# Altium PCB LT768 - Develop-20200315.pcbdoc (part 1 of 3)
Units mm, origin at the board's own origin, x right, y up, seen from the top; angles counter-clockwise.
Board outline 114.72 x 114.74 mm, 2 copper layers (Top Layer, Bottom Layer); 164 components, 138 nets, 704 pads, 858 vias.
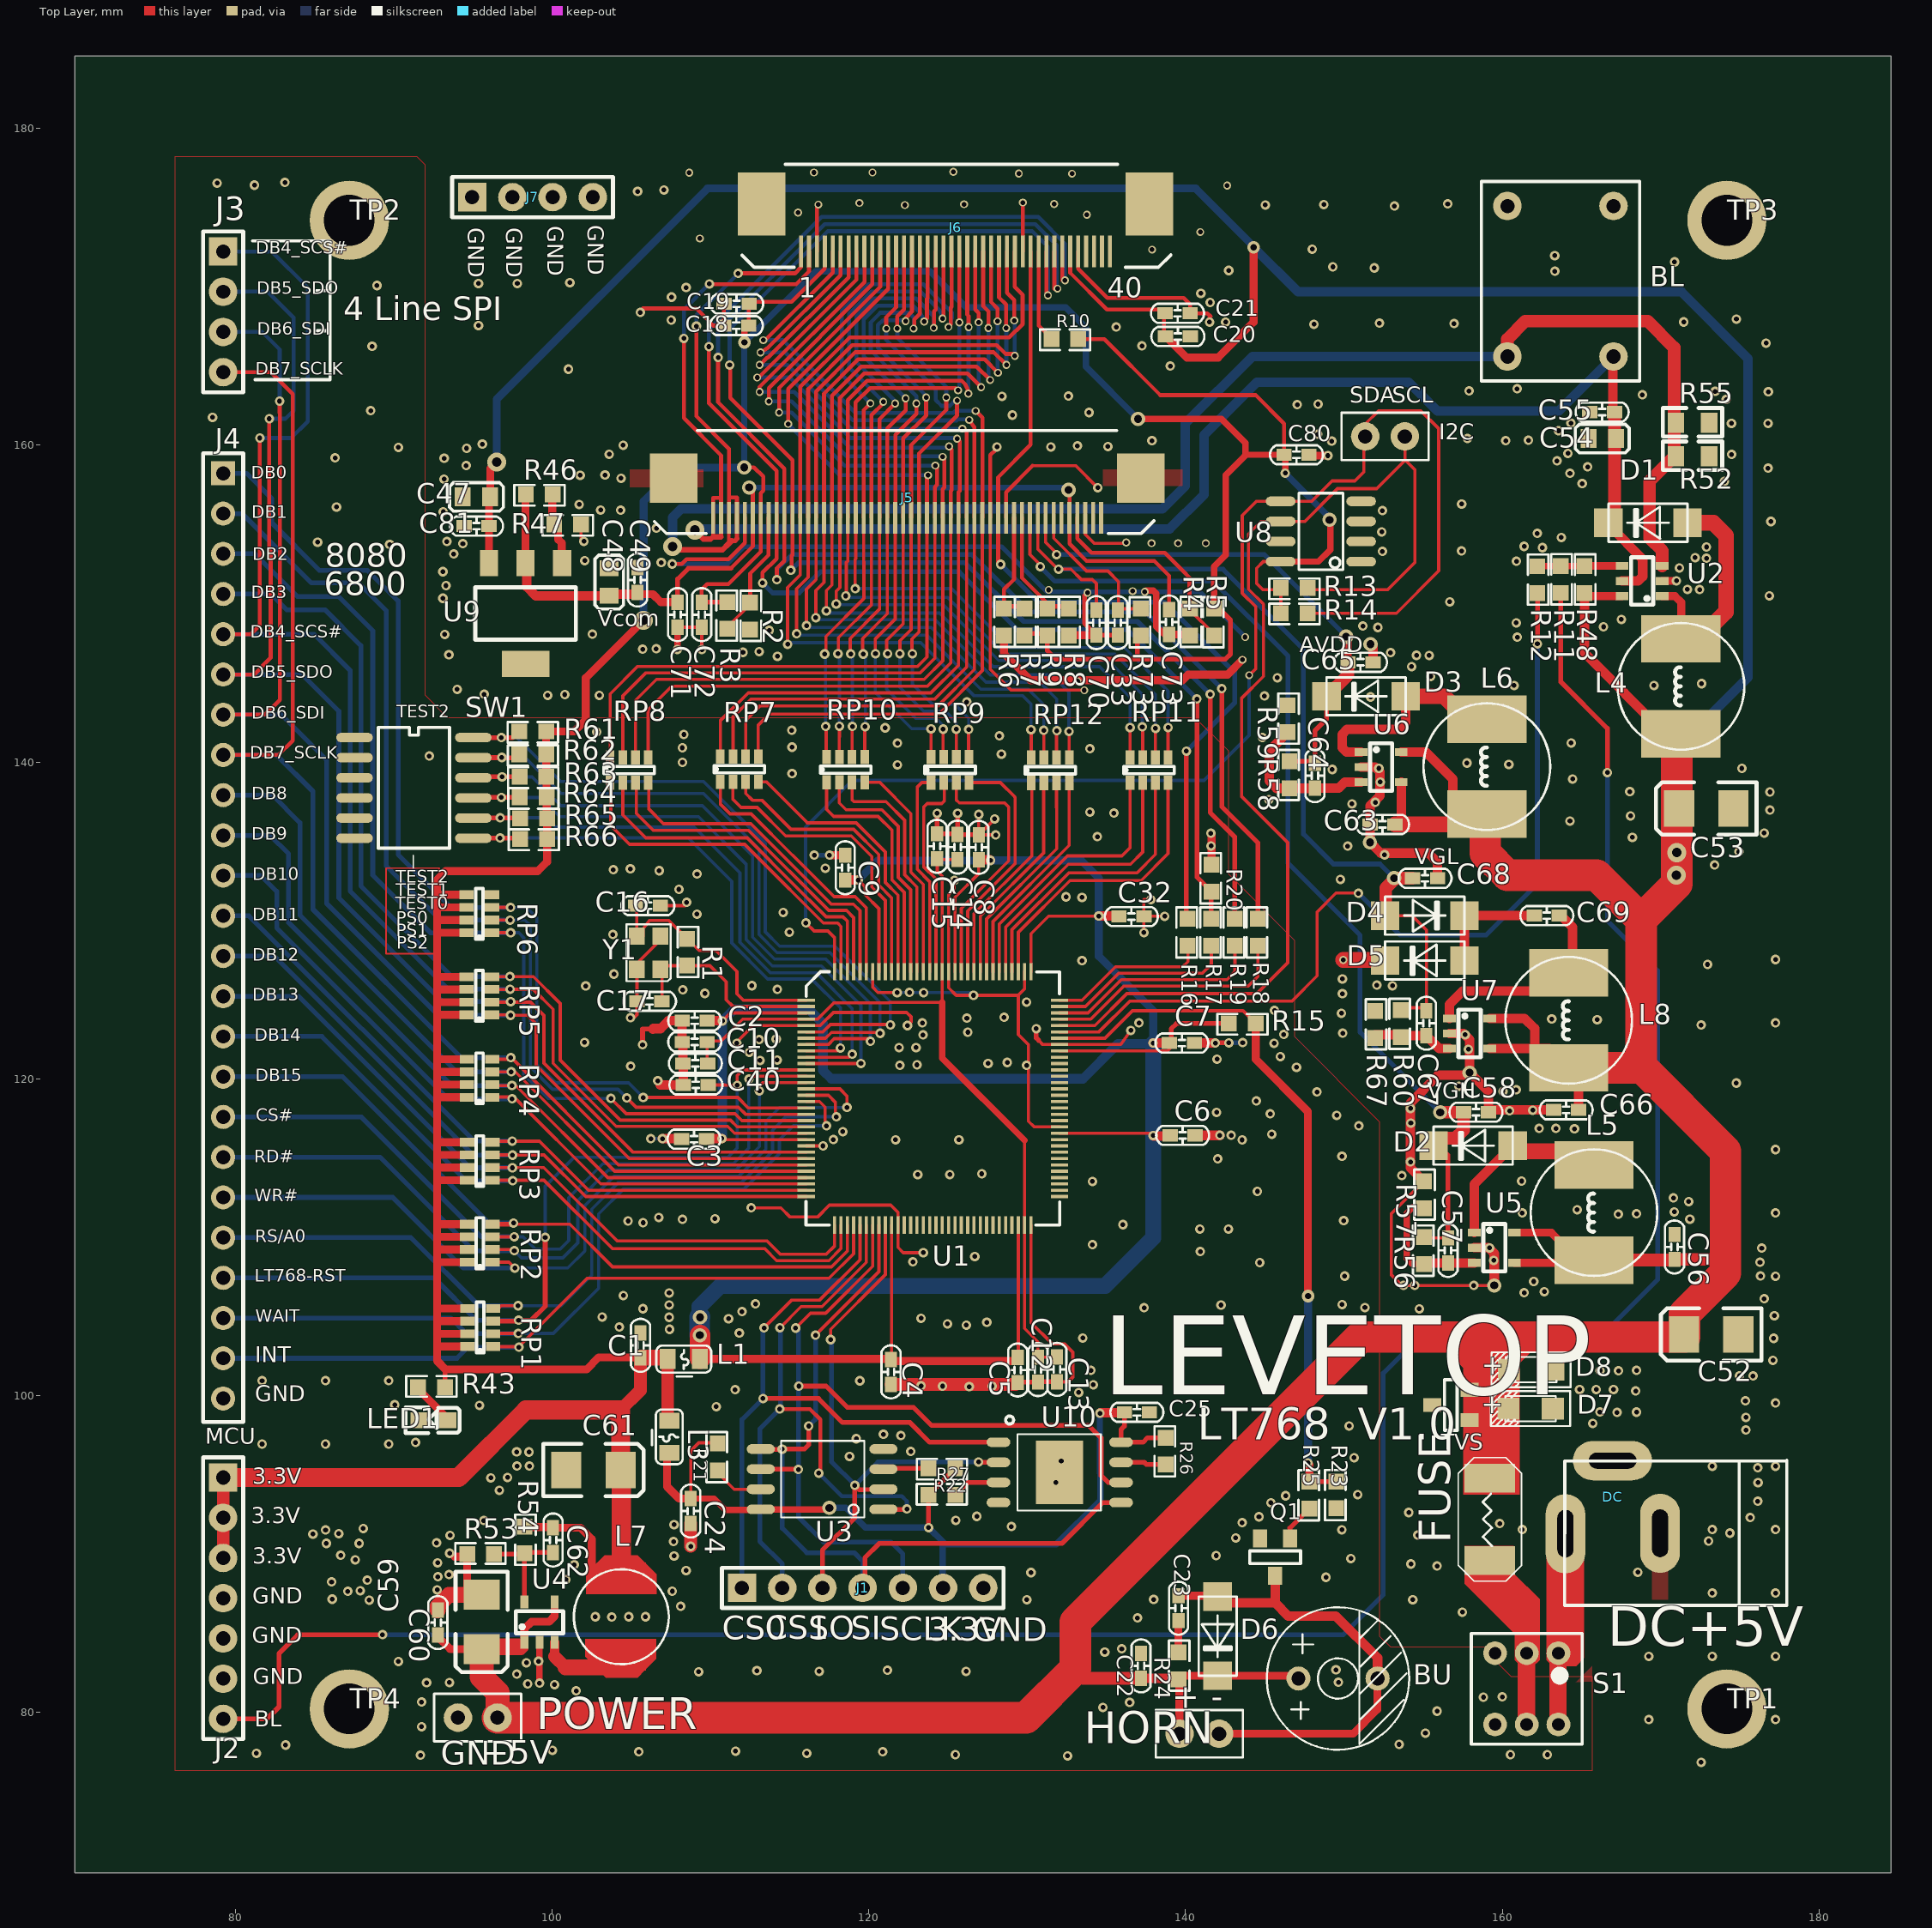
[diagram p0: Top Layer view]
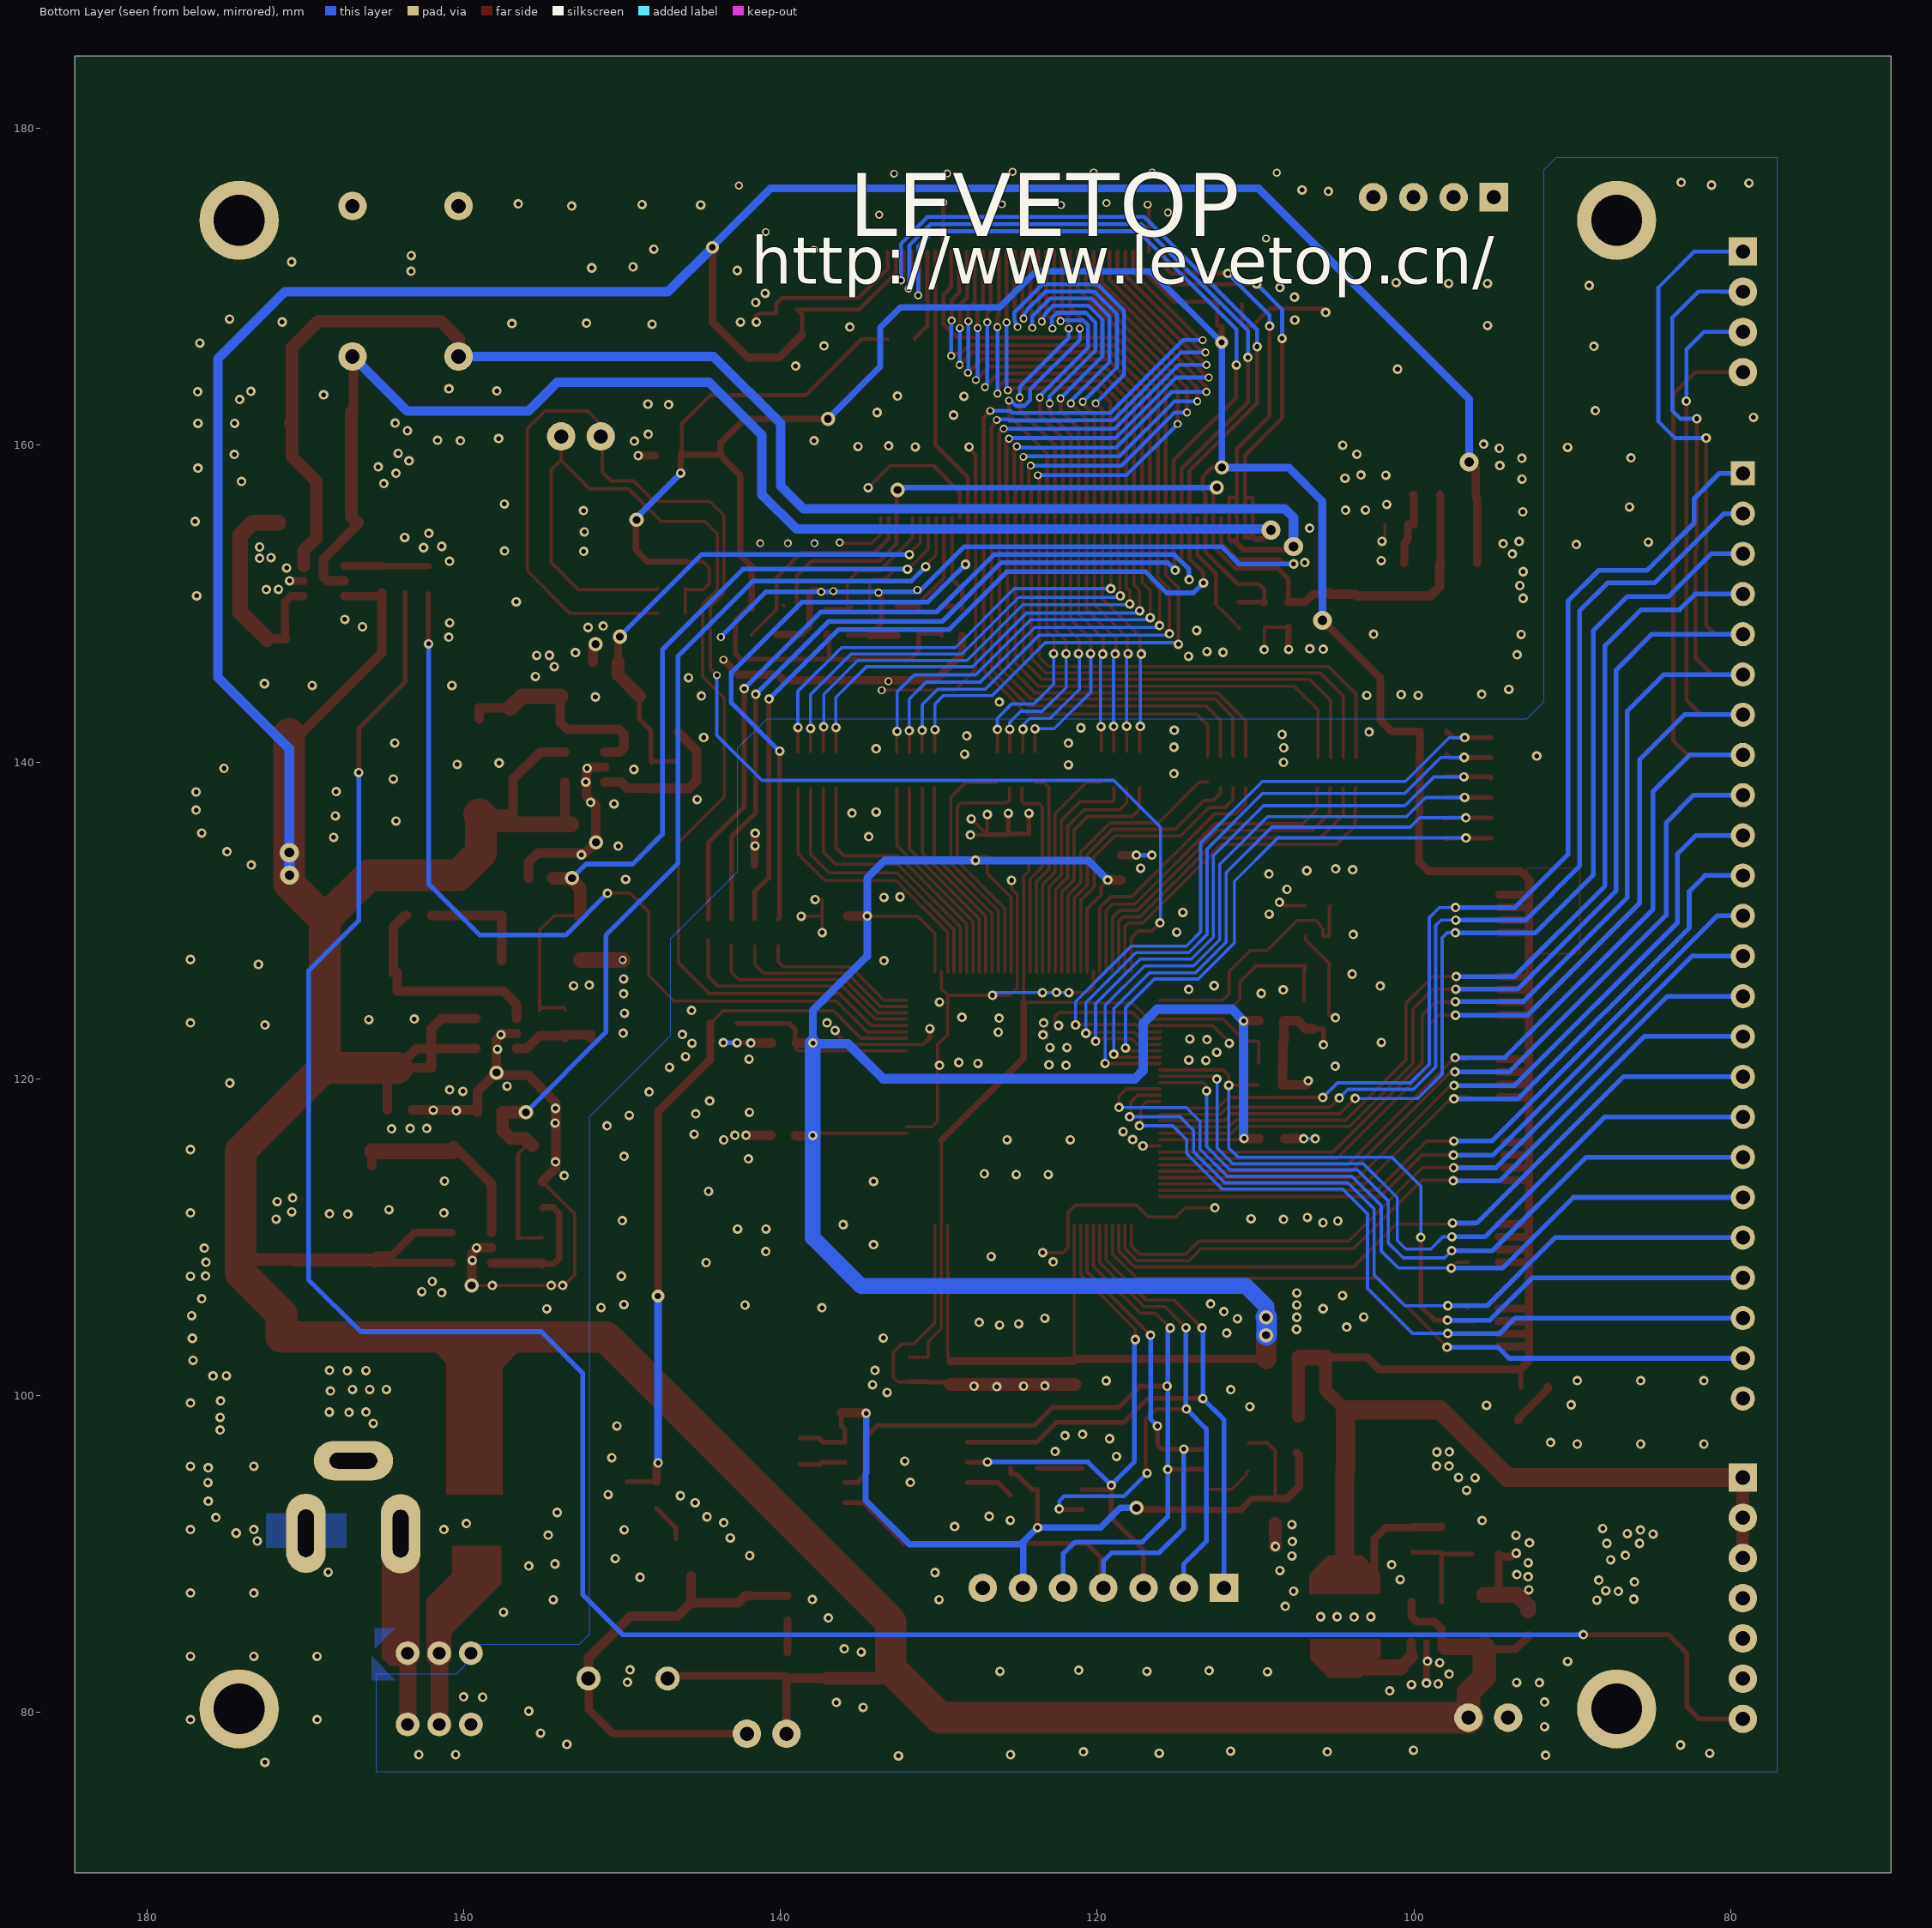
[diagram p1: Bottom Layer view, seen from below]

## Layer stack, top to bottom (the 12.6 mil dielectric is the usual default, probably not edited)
Top Solder: solder mask 0.0102, Solder Resist, Dk 3.5
Top Layer: signal copper 0.0356
Dielectric 1: dielectric 0.32, FR-4, Dk 4.8
Bottom Layer: signal copper 0.0356
Bottom Solder: solder mask 0.0102, Solder Resist, Dk 3.5

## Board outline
184.57,69.85 69.85,69.85 69.85,184.59 184.57,184.59

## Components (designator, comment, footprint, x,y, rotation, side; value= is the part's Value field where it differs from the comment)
BL "COM2" HA01 163.68,170.36 r0 top
BU "BUZ" BUZZER/9MM 149.63,82.13 r0 top
C1 "CAP0603" C0603 105.58,103.17 r90 top
C2 "CAP0603" C0603 109,123.666 r180 top
C3 "CAP0603" C0603 108.96,116.19 r180 top
C4 "CAP0603" C0603 121.4,101.49 r270 top
C5 "CAP0603" C0603 129.4,101.61 r270 top
C6 "CAP0603" C0603 139.819,116.426 r0 top
C7 "CAP0603" C0603 139.771,122.256 r0 top
C8 "CAP0603" C0603 126.944,134.613 r90 top
C9 "CAP0603" C0603 118.509,133.33 r90 top
C10 "CAP0603" C0603 109,122.326 r180 top
C11 "CAP0603" C0603 109.043,120.972 r180 top
C12 "CAP0603" C0603 130.68,101.63 r270 top
C13 "CAP0603" C0603 131.88,101.65 r270 top
C14 "CAP0603" C0603 125.605,134.633 r90 top
C15 "CAP0603" C0603 124.308,134.681 r90 top
C16 "CAP0603" C0603 106.05,130.93 r0 top
C17 "CAP0603" C0603 106.15,124.89 r0 top
C18 "CAP0603" C0603 111.63,167.56 r180 top
C19 "CAP0603" C0603 111.65,168.93 r180 top
C20 "CAP0603" C0603 139.52,166.87 r0 top
C21 "CAP0603" C0603 139.5,168.34 r0 top
C22 "CAP0603" C0603 137.19,82.93 r270 top
C23 "CAP0603" C0603 139.56,86.57 r90 top
C24 "CAP0603" C0603 108.751,92.703 r270 top
C25 "CAP0603" C0603 136.93,98.94 r0 top
C32 "CAP0603" C0603 136.584,130.243 r0 top
C33 "CAP0603" C0603 135.72,148.802 r270 top
C40 "CAP0603" C0603 109.074,119.611 r180 top
C47 "CAP0603" C0805 95.22,156.74 r180 top
C48 "CAP0603" C0805 103.603,151.369 r90 top
C49 "CAP0603" C0603 105.395,151.499 r90 top
C52 "E.CAP" 3528 173.2,103.85 r180 top
C53 "E.CAP" 3528 172.89,137.07 r180 top
C54 "CAP0603" C0805 166.32,160.43 r180 top
C55 "CAP0603" C0603 166.31,162.1 r180 top
C56 "CAP0603" C0603 170.88,109.38 r90 top
C57 "CAP0603" C0603 156.576,109.159 r270 top
C58 "CAP0603" C0603 158.346,117.889 r0 top
C59 "E.CAP" 3528 95.547,85.704 r270 top
C60 "CAP0603" C0603 92.78,85.66 r270 top
C61 "E.CAP" 3528 102.61,95.29 r0 top
C62 "CAP0603" C0603 100.06,90.87 r270 top
C63 "CAP0603" C0603 152.442,136.062 r180 top
C64 "CAP0603" C0603 148.173,139.141 r270 top
C65 "CAP0603" C0603 151.052,146.302 r0 top
C66 "CAP0603" C0603 164.039,118.033 r180 top
C67 "CAP0603" C0603 155.21,123.51 r270 top
C68 "CAP0603" C0603 155.13,132.66 r0 top
C69 "CAP0603" C0603 162.82,130.3 r180 top
C70 "CAP0603" C0603 134.37,148.802 r270 top
C71 "CAP0603" C0603 107.92,149.305 r270 top
C72 "CAP0603" C0603 109.45,149.305 r270 top
C73 "CAP0603" C0603 138.965,148.84 r270 top
C80 "CAP0603" C0603 147.013,159.402 r0 top
C81 "CAP0603" C0603 95.22,154.9 r180 top
D1 "DIOA" DO-214 169.21,155.11 r180 top
D2 "DIOA" DO-214 158.166,115.779 r180 top
D3 "DIOA" DO-214 151.402,144.152 r180 top
D4 "DIOA" DO-214 155.11,130.3 r0 top
D5 "DIOA" DO-214 155.11,127.47 r180 top
D6 "DIOA" DO-214 142.03,84.8 r270 top
D7 "DIODE-ZENER" TA/SMA 161.79,99.17 r0 top
D8 "DIODE-ZENER" TA/SMA 161.82,101.63 r0 top
DC "DCJACK" JACK/DC6 163.97,91.3 r270 top
FUSE "FUSE" FUSE/SMB 159.223,92.176 r90 top
HORN "COM2" JACK/2.54MM 139.62,78.64 r0 top
I2C "COM2" JACK/2.54MM 153.85,160.56 r180 top
J1 "COM7" COM7 111.99,87.85 r0 top
J2 "COM7" COM7 79.22,94.82 r270 top
J3 "COM4" SIP-4P 79.22,172.24 r270 top
J4 "COM24" SIP-24P 79.22,158.23 r270 top
J5 "COM50" FPC50-0.5 110.17,155.43 r0 top
J6 "COM40" FPC40-0.5 115.72,172.24 r0 top
J7 "COM4" SIP-4P 94.95,175.67 r0 top
L1 "47UH-CHOKE" L0805 108.311,102.312 r0 top
L3 "47UH-CHOKE" L0805 107.41,97.39 r270 top
L4 "47UH-CHOKE" IND8A 171.29,144.78 r90 top
L5 "47UH-CHOKE" IND8A 165.796,111.549 r90 top
L6 "47UH-CHOKE" IND8A 159.032,139.712 r90 top
L7 "47UH-CHOKE" IND6B 104.37,86.03 r180 top
L8 "47UH-CHOKE" IND8A 164.2,123.69 r90 top
LED1 "LED" LED-0603 92.5,98.43 r180 top
POWER "COM2" JACK/2.54MM 94.05,79.66 r0 top
Q1 "NPN_B1E2C3" SOT-23-1 145.66,89.79 r180 top
R1 "RES" R0603 108.527,127.99 r90 top
R2 "RES" R0603 112.5,149.22 r90 top
R3 "RES" R0603 111.07,149.26 r270 top
R4 "RES" R0603 140.29,148.84 r90 top
R5 "RES" R0603 141.81,148.84 r270 top
R6 "RES" R0603 128.53,148.84 r90 top
R7 "RES" R0603 129.84,148.84 r90 top
R8 "RES" R0603 132.63,148.84 r90 top
R9 "RES" R0603 131.28,148.84 r90 top
R10 "RES" R0603 132.38,166.71 r0 top
R11 "RES" R0603 163.697,151.529 r90 top
R12 "RES" R0603 162.22,151.51 r90 top
R13 "RES" R0603 146.87,150.99 r0 top
R14 "RES" R0603 146.87,149.4 r0 top
R15 "RES" R0603 143.58,123.49 r0 top
R16 "RES" R0603 140.13,129.25 r270 top
R17 "RES" R0603 141.63,129.25 r270 top
R18 "RES" R0603 144.56,129.25 r270 top
R19 "RES" R0603 143.1,129.25 r270 top
R20 "RES" R0603 141.64,132.67 r270 top
R21 "RES" R0603 110.45,96.12 r270 top
R22 "RES" R0603 124.61,95.4 r0 top
R23 "RES" R0603 149.516,93.724 r270 top
R24 "RES" R0603 139.55,82.93 r90 top
R25 "RES" R0603 147.828,93.713 r270 top
R26 "RES" R0603 138.748,96.486 r270 top
R27 "RES" R0603 124.621,93.711 r180 top
R43 "RES" R0603 92.387,100.526 r180 top
R46 "RES" R0603 99.192,156.887 r0 top
R47 "RES" R0603 100.98,155 r0 top
R48 "RES" R0603 165.19,151.52 r90 top
R52 "RES" R0805 172.02,159.3 r0 top
R53 "RES" R0603 95.483,89.973 r180 top
R54 "RES" R0603 98.26,90.88 r90 top
R55 "RES" R0805 172.02,161.41 r0 top
R56 "RES" R0603 155.066,109.159 r270 top
R57 "RES" R0603 155.046,112.669 r90 top
R58 "RES" R0603 146.562,139.192 r270 top
R59 "RES" R0603 146.452,142.732 r90 top
R60 "RES" R0603 153.581,123.477 r270 top
R61 "RES" R0603 98.77,141.93 r0 top
R62 "RES" R0603 98.78,140.47 r0 top
R63 "RES" R0603 98.79,139.07 r0 top
R64 "RES" R0603 98.8,137.76 r0 top
R65 "RES" R0603 98.83,136.45 r0 top
R66 "RES" R0603 98.83,135.14 r0 top
R67 "RES" R0603 151.982,123.426 r90 top
R73 "RES" R0603 137.17,148.84 r270 top
RP1 "RP4" 8R4R 95.46,104.296 r180 top
RP2 "RP4" 8R4R 95.431,109.615 r180 top
RP3 "RP4" 8R4R 95.43,114.795 r180 top
RP4 "RP4" 8R4R 95.41,120.03 r180 top
RP5 "RP4" 8R4R 95.4,125.24 r180 top
RP6 "RP4" 8R4R 95.4,130.42 r180 top
RP7 "RP4" 8R4R 111.819,139.546 r90 top
RP8 "RP4" 8R4R 104.86,139.5 r90 top
RP9 "RP4" 8R4R 125.129,139.508 r90 top
RP10 "RP4" 8R4R 118.536,139.517 r90 top
RP11 "RP4" 8R4R 137.696,139.49 r90 top
RP12 "RP4" 8R4R 131.457,139.481 r90 top
S1 "SW-SPST-NO" TURN 161.55,81.48 r270 top
SW1 "SWDIP" SW12 91.27,138.37 r0 top
TP1 "ATP" AP1 174.22,80.24 r0 top
TP2 "ATP" AP1 87.22,174.24 r0 top
TP3 "ATP" AP1 174.22,174.24 r0 top
TP4 "ATP" AP1 87.22,80.24 r0 top
TVS "TVS2" SOT-23-1 156.76,99.4 r90 top
U1 "LT768-136" LQFP128L 124.04,118.76 r90 top
U2 "SY7208" SOT23-6 168.84,151.43 r90 top
U3 "W25Q128JVSIQ" SOP8-208 120.92,92.81 r180 top
U4 "TD6817" SOT23-5 99.203,85.689 r0 top
U5 "LT1613" SOT23-5 159.506,109.329 r270 top
U6 "LT1613" SOT23-5 152.352,139.682 r270 top
U7 "LT1617" SOT23-5 157.94,122.86 r270 top
U8 "AT24C" SO8-OPT 148.55,154.56 r90 top
U9 "AMS1117" SOT223 98.32,149.38 r180 top
U10 "W25Q128JVSIQ" WSON8 128.19,97.05 r0 top
Y1 "CRYSTAL-3225" CRYSTAL-3225 106.09,127.96 r90 top

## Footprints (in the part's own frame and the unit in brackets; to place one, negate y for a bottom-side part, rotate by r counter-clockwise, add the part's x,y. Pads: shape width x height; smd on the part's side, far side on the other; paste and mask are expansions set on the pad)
8R4R [mm]
  rect 0.9x0.55 smd: 1(-0.8,1.2) 2(-0.8,0.4) 3(-0.8,-0.4) 4(-0.8,-1.2) 5(0.8,-1.2) 6(0.8,-0.4) 7(0.8,0.4) 8(0.8,1.2)
  silkscreen extent -0.23,-1.6 0.23,1.6
3528 [mil]
  rect 75x90 smd: 1(67.5,0) 2(-67.5,0)
  silkscreen extent -125,-65 125,65
AP1 [mm]
  round 5 hole 3.2: 1(-0.03,-0.03)
BUZZER/9MM [mil]
  round 60 hole 35: 1(-98.43,0) 2(98.43,0)
  silkscreen extent -177,-177 177,177
C0603 [mil]
  rect 38x30 smd: 1(-31,0) 2(31,0)
  silkscreen extent -66,-24 66,24
C0805 [mm]
  rect 1x1.2 smd: 1(-0.87,0) 2(0.87,0)
  silkscreen extent -1.7,-0.9 1.7,0.9
COM7 [mm]
  rect 1.8x1.8 hole 0.9: 1(0,0)
  round 1.8 hole 0.9: 2(2.54,0) 3(5.08,0) 4(7.62,0) 5(10.16,0) 6(12.7,0) 7(15.24,0)
  silkscreen extent -1.27,-1.27 16.51,1.27
CRYSTAL-3225 [mm]
  rect 1.1x1 smd: 1(-1.05,-0.75) 2(1.05,-0.75) 3(1.05,0.75) 4(-1.05,0.75)
  silkscreen extent -1.8,-1.4 1.8,1.4
DO-214 [mm]
  rect 1.8x1.8 smd: 1(-2.5,0) 2(2.5,0)
  silkscreen extent -2.5,-1.2 2.5,1.2
FPC40-0.5 [mm]
  rect 0.254x2 smd: 1(0,0) 2(0.5,0) 3(1,0) 4(1.5,0) 5(2,0) 6(2.5,0) 7(3,0) 8(3.5,0) 9(4,0) 10(4.5,0) 11(5,0) 12(5.5,0) 13(6,0) 14(6.5,0) 15(7,0) 16(7.5,0) 17(8,0) 18(8.5,0) 19(9,0) 20(9.5,0) 21(10,0) 22(10.5,0) 23(11,0) 24(11.5,0) 25(12,0) 26(12.5,0) 27(13,0) 28(13.5,0) 29(14,0) 30(14.5,0) 31(15,0) 32(15.5,0) 33(16,0) 34(16.5,0) 35(17,0) 36(17.5,0) 37(18,0) 38(18.5,0) 39(19,0) 40(19.5,0)
  rect 3x4 smd: 41(-2.5,3) 42(22,3)
  silkscreen extent -3.72,-1 23.36,5.5
FPC50-0.5 [mm]
  rect 0.254x2 smd: 1(0,0) 2(0.5,0) 3(1,0) 4(1.5,0) 5(2,0) 6(2.5,0) 7(3,0) 8(3.5,0) 9(4,0) 10(4.5,0) 11(5,0) 12(5.5,0) 13(6,0) 14(6.5,0) 15(7,0) 16(7.5,0) 17(8,0) 18(8.5,0) 19(9,0) 20(9.5,0) 21(10,0) 22(10.5,0) 23(11,0) 24(11.5,0) 25(12,0) 26(12.5,0) 27(13,0) 28(13.5,0) 29(14,0) 30(14.5,0) 31(15,0) 32(15.5,0) 33(16,0) 34(16.5,0) 35(17,0) 36(17.5,0) 37(18,0) 38(18.5,0) 39(19,0) 40(19.5,0) 41(20,0) 42(20.5,0) 43(21,0) 44(21.5,0) 45(22,0) 46(22.5,0) 47(23,0) 48(23.5,0) 49(24,0) 50(24.5,0)
  rect 3x3.1 smd: 51(-2.5,2.5) 52(27,2.5)
  silkscreen extent -3.72,-1 27.83,5.5
FUSE/SMB [mm]
  rect 1.8x3.2 smd: 1(-2.6,0) 2(2.6,0)
  silkscreen extent -3.9,-2 3.9,2
HA01 [mm]
  round 1.8 hole 0.9: 1(-3.35,-4.75) 2(3.35,-4.75) 3(3.35,4.75) 4(-3.35,4.75)
  silkscreen extent -5,-6.3 5,6.3
IND6B [mm]
  Top Layer region: 2.273,2.527 2.273,1.422 -2.184,1.422 -2.184,2.667 -1.55,3.301 -1.55,3.4 -1.451,3.4 -1.016,3.835 0.965,3.835 1.4,3.4 1.55,3.4 1.55,3.251
  Top Layer region: 1.527,-3.4 1.067,-3.861 -1.041,-3.861 -1.502,-3.4 -1.55,-3.4 -1.55,-3.352 -2.222,-2.68 -2.222,-1.422 2.235,-1.422 2.235,-2.692 1.55,-3.378 1.55,-3.4
  silkscreen extent -3,-3 3,3
IND8A [mm]
  rect 3x5 smd: 1(-3,0) 2(3,0)
  silkscreen extent -4,-4 4,4
JACK/2.54MM [mm]
  round 1.8 hole 0.9: 1(0,0) 2(2.5,0)
  silkscreen extent -1.5,-1.5 4,1.5
JACK/DC6 [mm]
  oval 5x2.5 hole 1 slot 3 at 0 deg: 1(0,6) 2(0.025,0.022)
  oval 2.5x5 hole 1 slot 3 at 90 deg: 3(-4.585,3)
  silkscreen extent -4.6,-0.03 4.56,14
L0805 [mil]
  rect 40x50 smd: 1(-40,0) 2(40,0)
  silkscreen extent -68,-44 68,33
LED-0603 [mm]
  rect 1.1x1 smd: 1(-0.9,0) 2(0.9,0)
  silkscreen extent -1.65,-0.82 1.75,0.8
LQFP128L [mm]
  rect 0.2x1.1 smd: 1(6.2,8) 2(5.8,8) 3(5.4,8) 4(5,8) 5(4.6,8) 6(4.2,8) 7(3.8,8) 8(3.4,8) 9(3,8) 10(2.6,8) 11(2.2,8) 12(1.8,8) 13(1.4,8) 14(1,8) 15(0.6,8) 16(0.2,8) 17(-0.2,8) 18(-0.6,8) 19(-1,8) 20(-1.4,8) 21(-1.8,8) 22(-2.2,8) 23(-2.6,8) 24(-3,8) 25(-3.4,8) 26(-3.8,8) 27(-4.2,8) 28(-4.6,8) 29(-5,8) 30(-5.4,8) 31(-5.8,8) 32(-6.2,8) 65(-6.2,-8) 66(-5.8,-8) 67(-5.4,-8) 68(-5,-8) 69(-4.6,-8) 70(-4.2,-8) 71(-3.8,-8) 72(-3.4,-8) 73(-3,-8) 74(-2.6,-8) 75(-2.2,-8) 76(-1.8,-8) 77(-1.4,-8) 78(-1,-8) 79(-0.6,-8) 80(-0.2,-8) 81(0.2,-8) 82(0.6,-8) 83(1,-8) 84(1.4,-8) 85(1.8,-8) 86(2.2,-8) 87(2.6,-8) 88(3,-8) 89(3.4,-8) 90(3.8,-8) 91(4.2,-8) 92(4.6,-8) 93(5,-8) 94(5.4,-8) 95(5.8,-8) 96(6.2,-8)
  rect 1.1x0.2 smd: 33(-8,6.2) 34(-8,5.8) 35(-8,5.4) 36(-8,5) 37(-8,4.6) 38(-8,4.2) 39(-8,3.8) 40(-8,3.4) 41(-8,3) 42(-8,2.6) 43(-8,2.2) 44(-8,1.8) 45(-8,1.4) 46(-8,1) 47(-8,0.6) 48(-8,0.2) 49(-8,-0.2) 50(-8,-0.6) 51(-8,-1) 52(-8,-1.4) 53(-8,-1.8) 54(-8,-2.2) 55(-8,-2.6) 56(-8,-3) 57(-8,-3.4) 58(-8,-3.8) 59(-8,-4.2) 60(-8,-4.6) 61(-8,-5) 62(-8,-5.4) 63(-8,-5.8) 64(-8,-6.2) 97(8,-6.2) 98(8,-5.8) 99(8,-5.4) 100(8,-5) 101(8,-4.6) 102(8,-4.2) 103(8,-3.8) 104(8,-3.4) 105(8,-3) 106(8,-2.6) 107(8,-2.2) 108(8,-1.8) 109(8,-1.4) 110(8,-1) 111(8,-0.6) 112(8,-0.2) 113(8,0.2) 114(8,0.6) 115(8,1) 116(8,1.4) 117(8,1.8) 118(8,2.2) 119(8,2.6) 120(8,3) 121(8,3.4) 122(8,3.8) 123(8,4.2) 124(8,4.6) 125(8,5) 126(8,5.4) 127(8,5.8) 128(8,6.2)
  silkscreen extent -8,-8.01 8,8.01
R0603 [mm]
  rect 1x1 smd: 1(-0.85,0) 2(0.85,0)
  silkscreen extent -1.57,-0.7 1.6,0.6
R0805 [mm]
  rect 1.05x1.27 smd: 1(-1.05,0) 2(1.05,0)
  silkscreen extent -1.88,-0.86 1.88,0.94
SIP-4P [mm]
  rect 1.8x1.8 hole 0.889: 1(0,0)
  round 1.8 hole 0.889: 2(2.54,0) 3(5.08,0) 4(7.62,0)
  silkscreen extent -1.27,-1.27 8.89,1.27
SIP-24P [mil]
  rect 60x60 hole 35: 1(0,0)
  round 60 hole 35: 2(100,0) 3(200,0) 4(300,0) 5(400,0) 6(500,0) 7(600,0) 8(700,0) 9(800,0) 10(900,0) 11(1000,0) 12(1100,0) 13(1200,0) 14(1300,0) 15(1400,0) 16(1500,0) 17(1600,0) 18(1700,0) 19(1800,0) 20(1900,0) 21(2000,0) 22(2100,0) 23(2200,0) 24(2300,0)
  silkscreen extent -50,-50 2358,50
SO8-OPT [mil]
  oval 24x74 smd: 1(-75,-100) 2(-25,-100) 3(25,-100) 4(75,-100) 5(75,100) 6(25,100) 7(-25,100) 8(-75,100)
  silkscreen extent -95,-55 95,55
SOP8-208 [mil]
  oval 70x24 smd: 1(0,0) 2(0,-50) 3(0,-100) 4(0,-150) 5(304.74,-150) 6(304.74,-100) 7(304.74,-50) 8(304.74,0)
  silkscreen extent 47,-170 254,20
SOT23-5 [mm]
  rect 0.5x0.8 smd: 1(-0.953,-1.27) 2(0,-1.27) 3(0.953,-1.27) 4(0.953,1.27) 5(-0.953,1.27)
  silkscreen extent -1.5,-0.7 1.5,0.7
SOT23-6 [mm]
  rect 0.5x0.8 smd: 1(-0.953,-1.27) 2(0,-1.27) 3(0.953,-1.27) 4(0.953,1.27) 5(0,1.27) 6(-0.953,1.27)
  silkscreen extent -1.5,-0.7 1.5,0.7
SOT223 [mil]
  rect 45x65 smd: 1(-91,-125) 2(0,-125) 3(91,-125)
  rect 118x65 smd: 4(0,125)
  silkscreen extent -125,-65 125,65
SOT-23-1 [mil]
  rect 35x45 smd: 1(-37.4,-46.26) 2(37.4,-46.26) 3(0,46.26)
  silkscreen extent -63,-16 63,16
SW12 [mm]
  oval 2.3x0.6 smd: 1(-3.75,3.175) 2(-3.75,1.905) 3(-3.75,0.635) 4(-3.75,-0.635) 5(-3.75,-1.905) 6(-3.75,-3.175) 7(3.75,-3.175) 8(3.75,-1.905) 9(3.75,-0.635) 10(3.75,0.635) 11(3.75,1.905) 12(3.75,3.175)
  silkscreen extent -2.25,-3.81 2.25,3.81
TA/SMA [mm]
  rect 1.4x1.4 smd: A(1.4,0) K(-1.4,0)
  silkscreen extent -2.5,-1.1 2.5,1.1
TURN [mm]
  round 1.5 hole 0.8: 1(-2.25,2) 2(-2.25,0) 3(-2.25,-2) 4(2.25,-2) 5(2.25,0) 6(2.25,2)
  silkscreen extent -3.5,-3.5 3.5,3.5
WSON8 [mm]
  oval 1.5x0.6 smd: 1(0,0) 2(0,-1.27) 3(0,-2.54) 4(0,-3.81) 5(7.74,-3.81) 6(7.74,-2.54) 7(7.74,-1.27) 8(7.74,0)
  rect 3x4 smd: 9(3.85,-1.9)
  silkscreen extent 0.45,-4.32 6.46,1.65

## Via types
v1: diameter 0.6, hole 0.3, Top Layer to Bottom Layer, 743 vias
v2: diameter 0.5, hole 0.3, Top Layer to Bottom Layer, 82 vias
v3: diameter 0.9, hole 0.5, Top Layer to Bottom Layer, 20 vias
v4: diameter 1.2, hole 0.6, Top Layer to Bottom Layer, 7 vias
v5: diameter 0.8, hole 0.4, Top Layer to Bottom Layer, 6 vias

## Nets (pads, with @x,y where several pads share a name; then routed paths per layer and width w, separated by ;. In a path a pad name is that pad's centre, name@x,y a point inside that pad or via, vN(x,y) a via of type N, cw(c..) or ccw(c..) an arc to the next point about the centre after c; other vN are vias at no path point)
$$$8246: D2.1 L5.2 U5.1 | length 12.9
  Top Layer w0.6: U5.1@158.236,110.281 158.236,113.349 D2.1@160.666,115.779 D2.1@160.666,115.427 ; L5.2@165.796,114.549 L5.2@165.796,115.427
  Top Layer w1: D2.1@160.666,115.427 L5.2@165.796,115.427
$$$8351: C57.2 R56.2 R57.1 U5.3 | length 8.6
  Top Layer w0.4: R57.1@155.046,111.819 154.975,111.89 154.35,111.89 153.97,111.51 153.97,108.639 154.3,108.309 R56.2@155.066,108.309
  Top Layer w0.6: R56.2@155.066,108.309 155.066,108.371 C57.2@156.576,108.371 156.576,108.376 U5.3@158.236,108.376
$$$8434: BU.2 C23.2 D6.1 HORN.2 Q1.3 | length 31.7
  Top Layer w0.5: C23.2@139.56,87.357 D6.1@141.973,87.357 ; HORN.2@142.12,78.64 150.58,78.64 152.11,80.17 152.11,82.11 BU.2@152.13,82.13 ; D6.1@141.973,87.357 D6.1@142.03,87.3 D6.1@141.973,87.357
  Top Layer w0.6: D6.1@141.973,87.357 142.213,87.357 142.67,86.9 145.66,86.9 ; BU.2@152.13,82.13 152.13,83.43 149.48,86.08 146.48,86.08 145.66,86.9 ; 145.66,86.9 Q1.3@145.66,88.615 145.66,86.9
$$$8717: D3.1 L6.2 U6.1 | length 14.3
  Top Layer w0.6: U6.1@151.082,140.634 150.154,140.634 149.89,140.899 149.89,141.75 150.2,142.06 153.46,142.06 153.902,142.502 D3.1@153.902,144.152 ; L6.2@157.06,143.422 159.032,143.422 L6.2@159.032,142.712
  Top Layer w1: D3.1@153.902,144.152 156.33,144.152 L6.2@157.06,143.422
$$$8718: C64.2 R58.2 R59.1 U6.3 | length 9.7
  Top Layer w0.6: R59.1@146.452,141.882 145.29,140.72 145.29,138.81 145.758,138.342 R58.2@146.562,138.342 148.173,138.342 C64.2@148.173,138.353 149.683,138.353 150.059,138.729 U6.3@151.082,138.729
$$$8972: C69.1 L8.2 U7.1 | length 14.2
  Top Layer w0.6: U7.1@156.67,123.813 156.67,124.71 157.5,125.54 164.2,125.54 L8.2@164.2,126.69 164.444,126.69 164.444,129.565 163.709,130.3 C69.1@163.607,130.3
$$$8973: C67.2 R60.2 R67.1 U7.3 | length 5.7
  Top Layer w0.6: R67.1@151.982,122.576 151.98,122.74 151.98,122.78 R60.2@153.69,122.78 ; U7.3@156.67,121.908 156.025,121.908 C67.2@155.21,122.723 153.69,122.723 R60.2@153.69,122.78 ; R60.2@153.69,122.78 R60.2@153.581,122.627 R60.2@153.69,122.78
$$$9412: C69.2 D4.2 D5.1 | length 7.3
  Top Layer w0.6: D5.1@157.61,127.47 D4.2@157.61,130.3 C69.2@162.033,130.3
$$$11143: C23.1 R24.2 | length 2
  Top Layer w0.5: R24.2@139.55,83.78 139.55,85.773 C23.1@139.56,85.783
$$$11355: R46.2 R47.1 U9.1 | length 4.9
  Top Layer w0.5: R46.2@100.042,156.887 99.98,156.78 100.005,156.78 100.005,155 R47.1@100.13,155 100.38,155 100.38,154.05 100.599,153.831 100.599,152.555 U9.1@100.631,152.555
$$$12340: Q1.1 R25.2 | length 2.4
  Top Layer w0.3: Q1.1@146.61,90.965 146.61,91.605 146.59,91.625 R25.2@147.828,92.863
$$$12717: FUSE.1 S1.2 S1.5 | length 6.8
  Top Layer w0.2: FUSE.1@159.223,89.576 159.223,87.23 161.55,84.903 S1.2@161.55,83.73
$$$13350: DC.2 S1.1 S1.6 | length 7.7
  Top Layer w0.2: S1.1@163.55,83.73 163.55,86.838 163.992,87.28 DC.2@163.992,91.275
$$$15520: C33.1 J5.44 R73.1 | length 17.1
  Top Layer w0.2: J5.44@131.67,155.43 131.67,154.14 133.75,152.06 135.1,152.06 135.77,151.39 135.77,150.834 ; C33.1@135.51,149.799 C33.1@135.72,149.589 ; C33.1@135.51,149.799 135.522,149.799 C33.1@135.51,149.799 ; C33.1@135.51,149.799 C33.1@135.72,149.589 ; C33.1@135.72,149.589 135.622,149.589 135.622,149.677 R73.1@137.166,149.677 ; C33.1@135.77,149.677 R73.1@137.166,149.677 ; C33.1@135.77,149.677 135.77,150.834 ; C33.1@135.77,149.677 135.77,150.834 ; C33.1@135.77,149.677 R73.1@137.166,149.677 ; C33.1@135.77,149.677 R73.1@137.166,149.677 ; C33.1@135.77,149.677 135.77,150.834 ; R73.1@137.166,149.677 R73.1@137.17,149.69 ; R73.1@137.166,149.677 R73.1@137.17,149.69 ; R73.1@137.166,149.677 R73.1@137.17,149.69 ; R73.1@137.166,149.677 R73.1@137.17,149.69
$$$20201: D1.1 L4.2 U2.1 | length 14.8
  Top Layer w0.5: U2.1@170.11,150.477 170.91,150.477 171.307,150.08 171.307,148.77 171.29,148.752 L4.2@171.29,147.78
  Top Layer w0.6: L4.2@171.29,147.78 L4.2@172.42,147.78
  Top Layer w1: D1.1@171.71,155.11 173.33,155.11 174.14,154.3 174.14,149.48 174.12,149.48 L4.2@172.42,147.78
$$$23973: U4.3 | length 7.4
  Top Layer w0.6: 100.156,83.519 U4.3@100.156,84.419
  Top Layer w0.8: 100.156,83.519 100.845,82.83
  Top Layer w1: 100.845,82.83 105.222,82.83 104.37,83.53
$$$24066: C62.2 R53.1 R54.1 U4.5 | length 7.2
  Top Layer w0.3: R53.1@96.333,89.973 R54.1@98.251,89.973 ; U4.5@98.251,86.959 R54.1@98.251,89.973 ; C62.2@100.06,90.083 98.26,90.083 R54.1@98.26,90.03 ; R54.1@98.251,89.973 R54.1@98.251,90.021 ; R54.1@98.251,89.973 R54.1@98.251,90.021 ; R54.1@98.251,89.973 R54.1@98.26,89.973 ; R54.1@98.251,89.973 R54.1@98.251,90.021 ; R54.1@98.251,89.973 R54.1@98.251,90.021 ; R54.1@98.251,89.973 R54.1@98.26,89.973 ; R54.1@98.251,90.021 R54.1@98.26,90.03 ; R54.1@98.251,90.021 R54.1@98.26,90.03 ; R54.1@98.251,90.021 R54.1@98.26,90.03 ; R54.1@98.251,90.021 R54.1@98.26,90.03 ; R54.1@98.26,89.973 R54.1@98.26,90.03 ; R54.1@98.26,89.973 R54.1@98.26,90.03
$$$29962: LED1.1 R43.2 | length 2.9
  Top Layer w0.5: R43.2@91.537,100.526 91.53,100.41 93.4,98.54 LED1.1@93.4,98.43
$$$31785: R11.2 R12.2 R48.2 U2.4 | length 5.4
  Top Layer w0.4: R12.2@162.22,152.36 162.239,152.379 R11.2@163.697,152.379 165.181,152.379 R48.2@165.19,152.37
  Top Layer w0.5: R48.2@165.19,152.37 165.202,152.382 U2.4@167.57,152.382
+5V: BU.1 C20.1 C21.1 C22.2 C47.1 C52.1 C53.1 C56.1 C59.1 C60.2 C63.1 C66.1 C81.1 D6.2 D7.K D8.K FUSE.2 HORN.1 J6.35 L4.1 L5.1 L6.1 L8.1 POWER.2 R24.1 R48.1 TVS.1 TVS.2 U2.6 U4.1 U4.4 U5.4 U5.5 U6.4 U6.5 U7.4 U7.5 U9.3 | length 926.3
  Top Layer w0.2: C59.1@95.547,84.158 97.99,84.158 U4.1@98.251,84.419 ; C56.1@170.64,108.549 170.684,108.593 C56.1@170.88,108.593 ; 174.037,108.593 174.1,108.53
  Top Layer w0.25: J6.35@132.72,172.24 132.72,170.89 135.04,168.57 138.99,168.57 138.943,168.57 C21.1@138.713,168.34 138.633,168.26 138.633,166.99 138.633,166.94 C20.1@138.733,166.87
  Top Layer w0.3: R24.1@139.487,82.143 R24.1@139.55,82.08 ; 133.55,82.25 133.55,82.143 133.55,82.25 ; 133.55,82.25 133.04,82.76 133.55,82.25
  Top Layer w0.5: C60.2@92.78,84.873 92.78,84.771 93.562,83.989 C59.1@95.547,83.989 ; U9.3@96.009,152.555 96.009,156.659 C47.1@96.09,156.74 ; U4.4@100.156,86.959 100.156,86.066 99.8,85.71 98.692,85.71 98.251,85.269 U4.1@98.251,84.419 ; HORN.1@139.62,78.64 139.62,82.01 R24.1@139.55,82.08 139.77,82.3 D6.2@142.03,82.3 146.96,82.3 BU.1@147.13,82.13 ; U5.4@160.776,108.376 L5.1@165.624,108.376 ; U5.5@160.776,110.281 163.11,110.281 164.551,108.84 165.505,108.84 L5.1@165.796,108.549 ; R48.1@165.19,150.477 U2.6@167.57,150.477 ; C59.1@95.547,83.989 95.686,83.85 98.061,83.85 98.251,84.04 U4.1@98.251,84.419 ; C59.1@95.547,83.989 C59.1@95.547,84.158 ; C59.1@95.547,83.989 C59.1@95.547,84.158 ; C59.1@95.547,84.158 95.547,84.419 U4.1@98.251,84.419 ; C47.1@96.09,156.74 v4@96.09,158.54 ; C47.1@96.09,156.74 v4@96.09,158.54 ; C47.1@96.09,156.74 v4@96.09,158.54 ; v4@96.09,158.54 v4(96.5,158.95) ; v4@96.09,158.54 v4(96.5,158.95) ; v4@96.09,158.54 v4(96.5,158.95) ; 140.083,165.54 138.633,166.99 140.083,165.54 ; 140.083,165.54 142.06,165.54 ; 140.083,165.54 142.06,165.54 ; 142.06,165.54 144.3,167.78 ; 142.06,165.54 144.3,167.78 ; 144.3,167.78 v5(144.3,172.5) 144.3,167.78
  Top Layer w0.6: C22.2@137.19,82.143 137.08,82.143 R24.1@139.487,82.143 ; C63.1@153.23,136.062 153.622,136.454 U6.4@153.622,138.729 ; U6.5@153.622,140.634 155.166,140.634 156.88,138.92 156.88,136.712 L6.1@159.032,136.712 ; U7.4@159.21,121.908 L8.1@162.05,121.908 ; U7.5@159.21,123.813 161.407,123.813 162.05,123.17 L8.1@162.05,121.908 ; C66.1@164.826,118.033 164.826,120.69 L8.1@164.2,120.69 ; R48.1@165.19,150.67 R48.1@165.19,150.477 ; L5.1@165.624,108.376 L5.1@165.796,108.549 ; L6.1@159.032,136.712 159.032,136.062 L6.1@159.032,136.712 ; L8.1@162.05,120.69 L8.1@162.05,121.908 ; L8.1@162.05,120.69 L8.1@164.2,120.69 ; L8.1@162.05,120.69 L8.1@164.2,120.69 ; L8.1@162.05,120.69 L8.1@162.05,121.908 ; L8.1@162.05,120.69 L8.1@162.05,121.908 ; L8.1@162.05,120.69 L8.1@164.2,120.69 ; L8.1@162.05,120.69 L8.1@164.2,120.69 ; L8.1@162.05,120.69 L8.1@162.05,121.908 ; L8.1@162.05,121.908 L8.1@162.982,121.908 ; L8.1@162.05,121.908 L8.1@162.982,121.908 ; L8.1@162.982,121.908 L8.1@164.2,120.69 ; L8.1@162.982,121.908 L8.1@164.2,120.69 ; 165.19,146.88 R48.1@165.19,150.477 ; 165.19,146.88 L4.1@170.29,141.78 ; 165.19,146.88 R48.1@165.19,150.477 ; 165.19,146.88 L4.1@170.29,141.78 ; L4.1@170.29,141.78 L4.1@171.03,141.78 ; L4.1@170.29,141.78 L4.1@171.03,141.78 ; L4.1@171.03,141.78 L4.1@171.29,141.78 ; L4.1@171.03,141.78 L4.1@171.29,141.78 ; L4.1@171.03,141.78 L4.1@171.29,141.78 ; L4.1@171.03,141.78 L4.1@171.29,141.78 ; L4.1@171.03,141.78 L4.1@171.29,141.78 ; L4.1@171.03,141.78 L4.1@171.29,141.78 ; L4.1@171.03,141.78 L4.1@171.29,141.78 ; L4.1@171.03,141.78 L4.1@171.29,141.78 ; L4.1@171.03,141.78 L4.1@171.29,141.78 ; L4.1@171.03,141.78 L4.1@171.29,141.78
  Top Layer w0.8: L5.1@165.796,108.549 C56.1@170.64,108.549 ; C56.1@170.88,108.593 174.037,108.593 ; 133.55,82.143 137.08,82.143 133.55,82.143
  Top Layer w1: L6.1@158.93,136.062 C63.1@153.23,136.062 L6.1@158.93,136.062 ; L6.1@158.93,136.062 159.032,136.062 L6.1@158.93,136.062
  Top Layer w1.5: C59.1@95.547,83.989 95.547,82.24 96.55,81.237 POWER.2@96.55,79.66
  Top Layer w2: POWER.2@96.55,79.66 129.94,79.66 133.04,82.76 ; FUSE.2@159.223,94.776 159.223,102.253 160.66,103.69 ; L8.1@164.2,120.69 168.4,120.69 168.625,120.915 ; 133.04,82.76 133.04,85.7 ; 133.04,82.76 133.04,85.7 ; 133.04,82.76 133.04,85.7 ; 133.04,85.7 151.03,103.69 ; 133.04,85.7 151.03,103.69 ; 133.04,85.7 151.03,103.69 ; 151.03,103.69 160.66,103.69 ; 151.03,103.69 160.66,103.69 ; 151.03,103.69 160.66,103.69 ; 158.93,134.25 L6.1@158.93,136.062 ; 158.93,134.25 160.32,132.86 ; 158.93,134.25 L6.1@158.93,136.062 ; 158.93,134.25 160.32,132.86 ; L6.1@158.93,136.062 L6.1@158.93,136.61 ; L6.1@158.93,136.062 L6.1@158.93,136.61 ; L6.1@158.93,136.61 L6.1@159.032,136.712 L6.1@158.93,136.61 ; 160.32,132.86 165.97,132.86 ; 160.32,132.86 165.97,132.86 ; 160.66,103.69 C52.1@171.52,103.69 ; 160.66,103.69 C52.1@171.52,103.69 ; 160.66,103.69 C52.1@171.52,103.69 ; 160.66,103.69 C52.1@171.52,103.69 ; 165.97,132.86 168.78,130.05 ; 165.97,132.86 168.78,130.05 ; 168.625,120.915 174.1,115.44 ; 168.625,120.915 168.78,121.07 ; 168.625,120.915 174.1,115.44 ; 168.625,120.915 168.78,121.07 ; 168.625,120.915 168.78,121.07 ; 168.625,120.915 174.1,115.44 ; 168.625,120.915 168.78,121.07 ; 168.625,120.915 174.1,115.44 ; 168.625,120.915 168.78,121.07 ; 168.625,120.915 174.1,115.44 ; 168.625,120.915 168.78,121.07 ; 168.78,121.07 168.78,130.05 ; 168.78,121.07 168.78,130.05 ; 168.78,121.07 168.78,130.05 ; 168.78,121.07 168.78,130.05 ; 168.78,121.07 168.78,130.05 ; 168.78,121.07 168.78,130.05 ; 168.78,130.05 v4@171.03,132.3 ; 168.78,130.05 v4@171.03,132.3 ; 168.78,130.05 v4@171.03,132.3 ; 168.78,130.05 v4@171.03,132.3 ; 168.78,130.05 v4@171.03,132.3 ; 168.78,130.05 v4@171.03,132.3 ; 168.78,130.05 v4@171.03,132.3 ; 168.78,130.05 v4@171.03,132.3 ; v4@171.03,132.3 L4.1@171.03,141.78 ; v4@171.03,132.3 L4.1@171.03,141.78 ; v4@171.03,132.3 L4.1@171.03,141.78 ; v4@171.03,132.3 L4.1@171.03,141.78 ; v4@171.03,132.3 L4.1@171.03,141.78 ; v4@171.03,132.3 L4.1@171.03,141.78 ; v4@171.03,132.3 L4.1@171.03,141.78 ; v4@171.03,132.3 L4.1@171.03,141.78 ; C52.1@171.52,103.69 171.52,105.15 ; C52.1@171.52,103.69 171.52,105.15 ; C52.1@171.52,103.69 171.52,105.15 ; C52.1@171.52,103.69 171.52,105.15 ; 171.52,105.15 174.1,107.73 ; 171.52,105.15 174.1,107.73 ; 171.52,105.15 174.1,107.73 ; 171.52,105.15 174.1,107.73 ; 174.1,107.73 174.1,108.53 ; 174.1,107.73 174.1,108.53 ; 174.1,107.73 174.1,108.53 ; 174.1,107.73 174.1,108.53 ; 174.1,108.53 174.1,115.44 ; 174.1,108.53 174.1,115.44 ; 174.1,108.53 174.1,115.44 ; 174.1,108.53 174.1,115.44 ; 174.1,108.53 174.1,115.44
  Bottom Layer w0.25: v4(171,132.86) v4@171.02,132.88
  Bottom Layer w0.5: v4(96.5,158.95) 96.5,162.91 ; v4(96.5,158.95) 96.5,162.91 ; v4(96.5,158.95) 96.5,162.91 ; 96.5,162.91 109.81,176.22 ; 96.5,162.91 109.81,176.22 ; 96.5,162.91 109.81,176.22 ; 109.81,176.22 140.64,176.22 ; 109.81,176.22 140.64,176.22 ; 109.81,176.22 140.64,176.22 ; 140.64,176.22 v5@144.3,172.56 ; 140.64,176.22 v5@144.3,172.56 ; 140.64,176.22 v5@144.3,172.56 ; v5(144.3,172.5) v5@144.3,172.56 ; v5(144.3,172.5) v5@144.3,172.56 ; v5(144.3,172.5) v5@144.3,172.56
  Bottom Layer w0.6: v5(144.3,172.5) 147.1,169.7 171.31,169.7 175.53,165.48 175.53,145.35 171.02,140.84 v4(171.02,134.28)
  Bottom Layer w0.7: v4@171.02,132.88 v4(171.02,134.28)
  other v4: 96.5,158.95
  other v5: 144.3,172.5
B0: J5.19 J6.21 RP11.5 | length 53.9
  Top Layer w0.2: v1(119.14,150.95) 119.14,152.8 119.17,152.83 J5.19@119.17,155.43 ; RP11.5@138.86,140.64 138.957,140.64 138.9,140.64 v1(138.9,142.18)
  Top Layer w0.25: J5.19@119.17,155.43 119.17,162.72 120.075,163.625 125.485,163.625 v2(125.64,163.47) ; v2(125.72,167.76) J6.21@125.72,172.24
  Bottom Layer w0.2: v1(119.14,150.95) 125.23,150.95 128.95,147.23 136.14,147.23 138.9,144.47 v1(138.9,142.18)
  Bottom Layer w0.25: v2(125.64,163.47) 125.72,163.55 v2(125.72,167.76)
B1: J5.18 J6.22 RP11.6 | length 56
  Top Layer w0.2: v1(118.54,150.49) 118.58,150.49 118.58,152.6 118.67,152.69 J5.18@118.67,155.43 ; RP11.6@138.096,140.64 138.1,140.64 v1(138.1,142.13)
  Top Layer w0.25: J5.18@118.67,155.43 118.67,162.856 119.894,164.08 125.868,164.08 126.1,163.848 126.355,163.29 v2(126.29,163.26) ; J6.22@126.22,172.24 126.22,168.24 126.3,168.16 v2(126.3,167.46)
  Bottom Layer w0.2: v1(118.54,150.49) 118.54,150.39 124.97,150.39 128.54,146.82 135.54,146.82 138.1,144.26 v1(138.1,142.13)
  Bottom Layer w0.25: v2(126.29,163.26) 126.29,164.37 126.3,164.38 v2(126.3,167.46)
B2: J5.17 J6.23 RP11.7 | length 57.2
  Top Layer w0.2: v1(117.94,149.98) 117.94,150.789 118.17,151.019 J5.17@118.17,155.43 ; v1(137.27,142.22) 137.27,142.06 137.33,142.06 137.296,142.026 RP11.7@137.296,140.64
  Top Layer w0.25: J5.17@118.17,155.43 118.17,162.993 119.707,164.53 126.23,164.53 v2(127.09,163.67) ; J6.23@126.72,172.24 126.72,168.58 126.94,168.36 v2(126.94,167.77)
  Bottom Layer w0.2: v1(117.94,149.98) 117.94,149.93 124.7,149.93 128.21,146.42 135.12,146.42 137.27,144.27 v1(137.27,142.22)
  Bottom Layer w0.25: v2(126.94,167.77) 126.94,163.82 v2(127.09,163.67)
B3: J5.16 J6.24 RP11.8 | length 58
  Top Layer w0.2: v1(117.32,149.55) 117.32,150.83 117.67,151.18 J5.16@117.67,155.43 ; RP11.8@136.496,140.64 136.496,142.024 v1(136.5,142.18)
  Top Layer w0.25: J5.16@117.67,155.43 117.67,163.13 119.52,164.98 126.8,164.98 v2(127.66,164.12) ; J6.24@127.22,172.24 127.22,168.78 127.55,168.45 v2(127.55,167.41)
  Bottom Layer w0.2: v1(117.32,149.55) 117.46,149.41 124.47,149.41 127.86,146.02 134.57,146.02 136.5,144.09 v1(136.5,142.18)
  Bottom Layer w0.25: v2(127.55,167.41) 127.55,164.2 127.63,164.12 v2(127.66,164.12)
B4: J5.15 J6.25 RP12.5 | length 56.2
  Top Layer w0.2: v1(116.65,149.12) 116.65,150.83 117.165,151.345 117.17,151.345 J5.15@117.17,155.43 ; v1(132.64,141.94) 132.64,141.95 132.657,141.967 RP12.5@132.657,140.631
  Top Layer w0.25: J5.15@117.17,155.43 117.17,163.27 119.33,165.43 127.31,165.43 v2(128.16,164.58) ; J6.25@127.72,172.24 127.72,169.046 128.13,168.636 v2(128.13,167.83)
  Bottom Layer w0.2: v1(116.65,149.12) 116.79,148.98 124.2,148.98 127.67,145.51 131.55,145.51 132.64,144.42 v1(132.64,141.94)
  Bottom Layer w0.25: v2(128.13,167.83) 128.13,164.61 v2(128.16,164.58)
B5: J5.14 J6.26 RP12.6 | length 56.8
  Top Layer w0.2: v1(116.06,148.62) 116.06,150.916 116.67,151.526 J5.14@116.67,155.43 ; RP12.6@131.857,140.631 131.857,141.967 v1(131.87,141.98)
  Top Layer w0.25: J5.14@116.67,155.43 116.67,163.406 119.144,165.88 127.89,165.88 v2(128.69,165.08) ; J6.26@128.22,172.24 128.22,169.338 128.66,168.898 128.66,167.4 v2(128.68,167.4)
  Bottom Layer w0.2: v1(116.06,148.62) 116.358,148.5 123.94,148.5 127.39,145.05 130.8,145.05 131.87,143.98 v1(131.87,141.98)
  Bottom Layer w0.25: v2(128.68,167.4) 128.68,165.08 v2(128.69,165.08)
B6: J5.13 J6.27 RP12.7 | length 57.6
  Top Layer w0.2: v1(115.44,148.1) 115.44,150.94 116.17,151.67 J5.13@116.17,155.43 ; v1(131.05,142) 131.057,141.993 RP12.7@131.057,140.631
  Top Layer w0.25: J5.13@116.17,155.43 116.17,163.55 118.95,166.33 128.08,166.33 128.64,165.77 129.22,165.77 v2(129.22,165.65) ; J6.27@128.72,172.24 128.72,169.63 129.19,169.16 v2(129.19,167.88)
  Bottom Layer w0.2: v1(115.44,148.1) 115.62,148.02 123.65,148.02 127.07,144.6 130.07,144.6 131.05,143.62 v1(131.05,142)
  Bottom Layer w0.25: v2(129.19,167.88) 129.22,167.88 v2(129.22,165.65)
B7: J5.12 J6.28 RP12.8 | length 57.1
  Top Layer w0.2: v1@114.871,147.441 114.871,151.02 115.67,151.819 J5.12@115.67,155.43 ; v1(130.24,142.04) 130.257,142.023 RP12.8@130.257,140.631
  Top Layer w0.25: J5.12@115.67,155.43 115.67,163.686 118.794,166.81 128.862,166.81 129.715,167.663 129.715,169.505 129.22,170 J6.28@129.22,172.24
  Bottom Layer w0.2: v1(114.87,147.44) 115.025,147.54 123.28,147.54 126.62,144.2 129.7,144.2 130.24,143.66 v1(130.24,142.04)
DE: J5.9 J6.34 R17.1 R20.2 | length 94.5
  Top Layer w0.2: R20.2@141.63,131.81 R20.2@141.64,131.82
  Top Layer w0.25: v1(109.9,166.23) 109.9,162.657 114.17,158.387 J5.9@114.17,155.43 114.17,152.845 113.29,151.965 v1(113.29,151.31) ; J6.34@132.22,172.24 132.22,170.42 v2(132.39,170.42)
  Top Layer w0.3: v1(140.72,143.98) 140.81,143.98 140.73,143.83 140.73,132.73 R20.2@141.64,131.82 ; R17.1@141.63,130.1 R20.2@141.63,131.81
  Bottom Layer w0.25: v1(109.9,166.23) 109.9,167.293 117.027,174.42 130.703,174.42 132.39,172.733 v2(132.39,170.42)
  Bottom Layer w0.3: v1(113.29,151.31) 113.92,150.68 115.61,150.68 116.94,152.01 125.71,152.01 129.35,148.37 136.33,148.37 v1(140.72,143.98)
FLASH_3.3V: C24.1 C25.1 J1.6 L3.2 R21.1 R22.2 R26.1 R27.2 U3.8 U10.8 | length 67.2
  Top Layer w0.2: C24.1@108.751,93.491 108.751,96.5 109.26,97.009 110.411,97.009 R21.1@110.45,96.97
  Top Layer w0.3: v1(134.59,98.88) 134.59,98.883 v1@134.62,98.913 ; C25.1@136.143,98.913 C25.1@136.143,98.94 136.143,98.061 135.93,97.848 U10.8@135.93,97.05 137.321,97.05 137.607,97.336 R26.1@138.748,97.336 ; R27.2@123.771,93.711 123.771,91.661 R27.2@123.771,93.711 ; R27.2@123.771,93.711 123.771,94.061 124.121,94.061 125.11,95.05 125.46,95.05 R22.2@125.46,95.4 ; R22.2@125.46,95.4 125.48,95.38 R22.2@125.46,95.4
  Top Layer w0.4: U3.8@113.189,92.796 U3.8@113.293,92.796 ; v3(117.51,92.9) 117.51,92.796 U3.8@113.293,92.796 ; 110.229,93.491 110.94,92.78 ; 110.229,93.491 C24.1@108.751,93.491 110.229,93.491 ; 110.229,93.491 110.94,92.78 ; 110.94,92.78 U3.8@113.31,92.78 ; 110.94,92.78 U3.8@113.31,92.78 ; U3.8@113.293,92.796 U3.8@113.31,92.78 ; U3.8@113.293,92.796 U3.8@113.31,92.78
  Top Layer w0.5: L3.2@107.41,96.374 107.25,96.214 107.25,94.25 108.009,93.491 C24.1@108.751,93.491
  Top Layer w0.6: v1@134.62,98.913 C25.1@136.143,98.913
  Bottom Layer w0.4: v3(117.51,92.9) 118.55,92.9 119.79,91.66 v1(123.77,91.66) 124.67,90.76 ; v1(134.59,98.88) 134.59,95.105 134.62,95.075 134.62,93.38 131.84,90.6 124.83,90.6 124.67,90.76 ; J1.6@124.67,87.85 124.67,90.76 ; J1.6@124.67,87.85 J1.6@124.69,87.85 J1.6@124.67,87.85 ; J1.6@124.67,87.85 124.67,90.76
  other v1: 123.77,91.66
FLASH_SPI_CS0: J1.1 U1.37 U10.1 | length 55.7
  Top Layer w0.2: v1(113.38,104.27) 115.14,106.03 116.9,106.03 119.44,108.57 U1.37@119.44,110.76
  Top Layer w0.3: v1(113.32,99.81) 116.82,99.81 118.34,98.29 122.6,98.29 123.84,97.05 U10.1@128.19,97.05
  Bottom Layer w0.3: 111.99,98.48 v1(113.32,99.81) ; 111.99,98.48 J1.1@111.99,87.85 111.99,98.48 ; 111.99,98.48 v1(113.32,99.81) ; v1(113.32,99.81) 113.32,104.13 113.41,104.22 v1(113.38,104.27) ; v1(113.38,104.27) v1@113.434,104.27 ; v1(113.38,104.27) v1@113.434,104.27 ; v1@113.434,104.27 113.454,104.25 v1@113.434,104.27
  other v1: 113.38,104.27
FLASH_SPI_CS1: J1.2 U1.38 U3.1 | length 54.2
  Top Layer w0.2: v1(114.39,104.28) 115.72,105.61 117.046,105.61 119.84,108.404 U1.38@119.84,110.76 ; v1(116.84,95.1) v1@116.936,95.1 ; v1@122.37,92.81 v1(122.4,92.84)
  Top Layer w0.25: v1(114.37,99.15) 116.276,99.15 116.936,98.49 v1@116.936,95.1
  Top Layer w0.3: U3.1@120.92,92.81 v1@122.37,92.81
  Bottom Layer w0.2: v1(114.37,99.15) v1@114.41,99.17 ; v1@114.41,99.17 114.385,99.145 v1@114.41,99.17
  Bottom Layer w0.25: v1(116.84,95.1) 118.3,93.64 122.09,93.64 122.4,93.33 v1(122.4,92.84)
  Bottom Layer w0.3: v1(114.39,104.28) 114.41,104.2 v1@114.41,99.17 ; 113.11,90.79 114.53,89.37 ; 113.11,90.79 113.11,97.89 ; 113.11,90.79 113.11,97.89 ; 113.11,90.79 114.53,89.37 ; 113.11,97.89 v1(114.37,99.15) ; 113.11,97.89 v1(114.37,99.15) ; v1(114.37,99.15) 114.385,99.145 v1(114.37,99.15) ; 114.53,89.37 J1.2@114.53,87.85 114.53,89.37
  other v1: 114.37,99.15 114.37,99.15
FLASH_SPI_SCLK: J1.5 U1.39 U3.6 U10.6 | length 84.1
  Top Layer w0.2: v1(115.38,104.26) 116.32,105.2 117.272,105.2 120.24,108.168 U1.39@120.24,110.76
  Top Layer w0.3: U3.6@113.19,95.36 v1@115.52,95.36 ; U3.6@113.19,95.36 U3.6@113.18,95.35 U3.6@113.19,95.36 ; U3.6@113.19,95.36 v1@115.52,95.36 ; v1@115.52,95.36 v1(115.55,95.33) ; v1@115.52,95.36 v1(115.55,95.33) ; v1(115.55,95.33) 115.55,95.333 v1(115.55,95.33) ; 117.3,100.59 118.65,99.24 ; 117.3,100.59 v1(115.58,100.59) 117.3,100.59 ; 117.3,100.59 118.65,99.24 ; 118.65,99.24 122.83,99.24 ; 118.65,99.24 122.83,99.24 ; 122.83,99.24 123.97,98.1 ; 122.83,99.24 123.97,98.1 ; 123.97,98.1 133.89,98.1 ; 123.97,98.1 133.89,98.1 ; 133.89,98.1 134.67,97.32 ; 133.89,98.1 134.67,97.32 ; 134.67,94.95 135.11,94.51 ; 134.67,94.95 134.67,97.32 ; 134.67,94.95 135.11,94.51 ; 134.67,94.95 134.67,97.32 ; 135.11,94.51 U10.6@135.93,94.51 135.11,94.51 ; U3.6@113.189,95.333 113.189,95.336 U3.6@113.189,95.333
  Bottom Layer w0.3: v1(115.38,104.26) 115.55,104.09 v1@115.55,100.59 ; J1.5@122.15,87.85 122.15,89.99 121.39,90.75 117.14,90.75 115.55,92.34 v1(115.55,95.33) v1@115.55,100.59 ; v1@115.55,100.59 v1(115.58,100.59) v1@115.55,100.59
  other v1: 115.55,95.33 115.55,95.33 115.58,100.59
FLASH_SPI_SI: J1.4 U1.40 U3.5 U10.5 | length 63.8
  Top Layer w0.2: v1(116.63,103.81) 120.64,107.82 U1.40@120.64,110.76
  Top Layer w0.3: U3.5@113.189,96.606 114.562,96.606 v1(114.53,96.61) 115.93,96.61 116.2,96.88 v1(116.2,98.07) ; J1.4@119.61,87.85 119.75,87.85 119.75,89.75 120.65,90.65 132.19,90.65 134.78,93.24 U10.5@135.93,93.24
  Bottom Layer w0.3: v1(116.2,98.07) 116.63,98.5 v1(116.63,103.81) ; 114.53,91.62 116.08,90.07 ; 114.53,91.62 v1(114.53,96.61) 114.53,91.62 ; 114.53,91.62 116.08,90.07 ; 116.08,90.07 119.08,90.07 ; 116.08,90.07 119.08,90.07 ; 119.08,90.07 119.61,89.54 ; 119.08,90.07 119.61,89.54 ; 119.61,89.54 J1.4@119.61,87.85 119.61,89.54
  other v1: 114.53,96.61
FLASH_SPI_SO: J1.3 U1.41 U3.2 U10.2 | length 52.5
  Top Layer w0.2: v1(117.59,103.53) 117.59,104.18 121.04,107.63 U1.41@121.04,110.76
  Top Layer w0.3: U3.2@120.929,94.066 119.64,94.06 119.39,94.06 119.12,94.33 v1(119.11,94.33) ; U10.2@128.19,95.78 v1@127.06,95.78 ; J1.3@117.07,87.85 117.07,90.23 ; J1.3@117.07,87.85 117.07,90.23 ; J1.3@117.07,87.85 117.07,90.23 ; 117.07,90.23 119.11,92.27 ; 117.07,90.23 119.11,92.27 ; 117.07,90.23 119.11,92.27 ; 119.11,92.27 v1(119.11,94.33) ; 119.11,92.27 v1(119.11,94.33) ; 119.11,92.27 v1(119.11,94.33) ; v1(126.93,95.8) v1@127.01,95.78 ; v1(126.93,95.8) v1@127.01,95.78 ; v1(126.93,95.8) 127.04,95.8 v1@127.06,95.78 ; v1@127.01,95.78 v1@127.06,95.78 ; v1@127.01,95.78 v1@127.06,95.78
  Bottom Layer w0.3: v1(126.93,95.8) 120.58,95.8 v1(119.11,94.33) 119.11,94.35 117.64,95.82 117.64,103.257 v1(117.59,103.53) ; v1(117.59,103.53) 117.64,103.48 v1(117.59,103.53)
  other v1: 119.11,94.33 119.11,94.33
G0: J5.27 J6.13 RP9.5 | length 38.3
  Top Layer w0.2: v1(122.75,146.84) 122.72,146.84 122.72,147.77 123.17,148.22 J5.27@123.17,155.43 ; v1(126.3,142.06) 126.3,140.658 RP9.5@126.329,140.658
  Top Layer w0.25: v2(121.1,167.37) 121.1,168.09 121.72,168.71 J6.13@121.72,172.24 ; J5.27@123.17,155.43 123.17,157.311 123.165,157.316 123.165,159.484 125.57,161.889 v2(125.57,162.82)
  Bottom Layer w0.2: v1(122.75,146.84) 122.75,144.92 124.01,143.66 125.41,143.66 126.309,142.761 126.309,142.069 v1(126.3,142.06)
  Bottom Layer w0.25: v2(121.1,167.37) 121.1,166.66 124.23,163.53 124.23,162.85 124.59,162.49 125.121,162.49 125.451,162.82 v2(125.57,162.82)
G1: J5.26 J6.14 RP9.6 | length 36.5
  Top Layer w0.2: v1(121.96,146.84) 121.96,147.66 122.67,148.37 J5.26@122.67,155.43 ; v1(125.52,142.07) 125.52,140.658 RP9.6@125.529,140.658
  Top Layer w0.25: v2(121.8,167.37) 121.79,167.37 121.79,167.64 121.79,168.142 122.22,168.572 J6.14@122.22,172.24 ; J5.26@122.67,155.43 122.67,160.007 124.89,162.227 v2(124.89,163.02)
  Bottom Layer w0.2: v1(121.96,146.84) 121.96,144.71 123.47,143.2 124.83,143.2 125.52,142.51 v1(125.52,142.07)
  Bottom Layer w0.25: v2(121.8,167.37) 121.8,166.78 124.89,163.69 v2(124.89,163.02)
G2: J5.25 J6.15 RP9.7 | length 38.1
  Top Layer w0.2: v1(121.18,146.84) 121.12,146.84 121.12,147.685 122.17,148.735 J5.25@122.17,155.43 ; v1(124.69,142.08) 124.69,140.658 RP9.7@124.729,140.658
  Top Layer w0.25: J5.25@122.17,155.43 122.17,160.44 123.62,161.89 v2(123.62,163.02) ; v2(122.32,167.84) 122.32,168.035 122.72,168.435 J6.15@122.72,172.24
  Bottom Layer w0.2: v1(121.18,146.84) 121.12,146.79 121.12,144.6 122.97,142.75 124.26,142.75 124.69,142.32 v1(124.69,142.08)
  Bottom Layer w0.25: v2(122.32,167.84) 122.32,167.9 120.888,167.9 120.575,167.587 120.575,166.172 123.673,163.073 v2(123.62,163.02)
G3: J5.24 J6.16 RP9.8 | length 40.8
  Top Layer w0.2: v1(120.42,146.84) 120.4,146.84 120.4,147.76 121.67,149.03 J5.24@121.67,155.43 ; RP9.8@123.93,140.658 v1(123.93,142.1)
  Top Layer w0.25: J5.24@121.67,155.43 121.67,160.656 123,161.986 v2(123,162.64) ; v2(122.83,167.37) 122.83,167.432 122.878,167.48 122.878,167.95 123.22,168.292 J6.16@123.22,172.24
  Bottom Layer w0.2: v1(123.93,142.1) 122.71,142.1 120.4,144.41 v1@120.4,146.76 ; v1@120.36,146.73 v1@120.39,146.76 ; v1@120.36,146.73 v1(120.42,146.84) ; v1@120.36,146.73 v1(120.42,146.84) ; v1@120.36,146.73 v1@120.39,146.76 ; v1@120.39,146.76 v1@120.4,146.76 ; v1@120.39,146.76 v1@120.4,146.76 ; v1@120.4,146.76 v1(120.42,146.84)
  Bottom Layer w0.25: v2(122.83,167.37) 122.85,167.37 122.85,168.052 122.532,168.37 120.721,168.37 120.12,167.769 120.12,165.987 123,163.107 v2(123,162.64)
  other v1: 120.42,146.84
G4: J5.23 J6.17 RP10.5 | length 39.3
  Top Layer w0.2: v1(119.65,146.82) 119.61,146.82 119.61,147.8 121.17,149.36 J5.23@121.17,155.43 ; RP10.5@119.736,140.667 119.74,140.667 119.74,142.17 119.751,142.232 v1(119.76,142.23)
  Top Layer w0.25: J5.23@121.17,155.43 121.17,161.064 122.32,162.214 v2(122.32,162.97) ; v2(123.49,167.82) 123.67,168 123.67,169.26 123.72,169.31 J6.17@123.72,172.24
  Bottom Layer w0.2: v1(119.65,146.82) 119.61,146.75 119.685,146.675 119.785,146.675 119.785,142.255 v1(119.76,142.23)
  Bottom Layer w0.25: v2(123.49,167.82) 123.532,167.844 123.24,168.365 122.785,168.82 120.535,168.82 119.67,167.955 119.67,167.64 119.67,165.62 v2(122.32,162.97) ; v2@122.282,162.932 v2(122.32,162.97) ; v2@122.282,162.932 122.282,162.84 v2@122.282,162.932 ; v2@122.282,162.932 v2(122.32,162.97)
